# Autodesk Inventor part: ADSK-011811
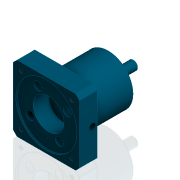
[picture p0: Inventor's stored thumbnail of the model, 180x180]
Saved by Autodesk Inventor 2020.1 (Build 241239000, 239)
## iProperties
Created: 1999-12
Part Number: ADSK-011811
Material: Acier doux
Description: REDUCER,PLANETARY,10/1
Document SubType Name: Modeling
Designer: sspink
Density: 7.86 g/cm^3
Appearance: Bearing Blue
Mass: 6821.52 g
Surface Area: 841.64 cm^2
Volume: 867.878 cm^3
Control State: 0
Checked Out: False
Master: False
Shininess: 0.0
Length Units: 11269
Angle Units: 11279
Time Units: 11290
Mass Units: 11283
Length Display Precision: 3
Angle Display Precision: 2
Compacted: True
Dimensions: 120x120x158 mm
Mass: 6,822 kg
Density: 0.0
Volumn: 0.0
Area: 0.0
PropertySet Name: Model Information
Title: A105198
Author: sspink
Revision Number: -
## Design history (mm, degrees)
node "Solide1"
  node "Extrusion1" dims "d1" = 80, "d2" = 0
  node "Extrusion2" dims "d7" = 32, "d8" = 0
  node "Extrusion3" dims "d12" = 5, "d13" = 0
  node "Extrusion4" dims "d15" = 5, "d16" = 0
  node "Extrusion5" dims "d18" = 36, "d19" = 0
  node "Hole1" dims "d21" = 4.917, "d22" = 4, "d23" = 2, "d24" = 60 deg, "d25" = 16, "d26" = 118 deg, "d65" = 12
  node "Extrusion6" dims "d36" = 32, "d37" = 0
  node "Hole2" dims "d38" = 6.917, "d39" = 9.525, "d40" = 6.35, "d41" = 60 deg, "d42" = 24, "d43" = 118 deg, "d66" = 20
  node "Hole3" dims "d44" = 6, "d45" = 15, "d46" = 23, "d47" = 60 deg, "d48" = 32, "d49" = 118 deg
  node "Extrusion7" dims "d52" = 32, "d53" = 0
  node "Extrusion8" dims "d54" = 4, "d55" = 0
  node "Hole4" dims "d57" = 12, "d58" = 15, "d59" = 23, "d60" = 60 deg, "d61" = 60, "d62" = 118 deg
  node "Chamfer2" dims "d27" = 1, "d28" = 1, "d63" = 45 deg
  node "Chamfer3" dims "d29" = 1, "d30" = 1, "d64" = 45 deg
sketch "Sketch5"
  geometry: C1 r 20 at (0, 0) reference; C2 r 8.25 at (0, 0)
  constraints: 1 centre point, 1 coincident
  dimensions: "d17" = 16.5 diameter of C2
sketch "Sketch6"
  geometry: L1 (0, 0)-(40, 0); L2 (0, 0)-(0, 40); L3 (0, 0)-(-40, 0); L4 (0, 0)-(0, -40); C1 r 45 at (0, 0) reference; A1 r 40 centre (0, 0) between (40, 0) and (0, 40); 4 further points
  constraints: 8 end point, 5 coincident, 4 point on circle, 3 perpendicular, 1 centre point, 1 horizontal
  dimensions: "d20" = 80 diameter of A1
workaxis "Work Axis1"
sketch "Sketch7"
  geometry: L1 (-60, 60)-(60, 60) reference; L2 (-60, -60)-(-60, 60) reference; L3 (60, -60)-(-60, -60) reference; L4 (60, 60)-(60, -60) reference; L5 (-60, 60)-(60, -60); L6 (60, 60)-(-60, -60); L7 (-34.641, 60)-(34.641, -60); L8 (60, 34.641)-(-60, -34.641); A1 r 65 centre (0, 0) between (-45.962, 45.962) and (-45.962, -45.962); A2 r 39 centre (0, 0) between (33.775, 19.5) and (19.5, -33.775); A3 r 80 centre (0, 0) between (-52.915, 60) and (-60, 52.915); A4 r 80 centre (0, 0) between (60, 52.915) and (52.915, 60); A5 r 80 centre (0, 0) between (-60, -52.915) and (-52.915, -60); A6 r 80 centre (0, 0) between (52.915, -60) and (60, -52.915); 5 further points
  constraints: 20 point on line, 16 point on circle, 8 end point, 6 centre point, 3 coincident, 3 concentric, 2 midpoint, 2 perpendicular
  dimensions: "d32" = 80 radius of A3; "d33" = 15 deg angle of L5 L7; "d34" = 130 diameter of A1; "d35" = 78 diameter of A2
node "Corps solides"
node "Corps surfaciques"
sketch "Sketch8"
  geometry: C1 r 28 at (0, 0); C2 r 55.5 at (0, 0); A1 r 80 centre (0, 0) between (-60, -52.915) and (-52.915, -60) reference
  constraints: 2 centre point, 2 coincident
  dimensions: "d50" = 56 diameter of C1; "d51" = 111 diameter of C2
sketch "Sketch1"
  geometry: C1 r 45 at (0, 0)
  constraints: 1 centre point, 1 other
  dimensions: "d0" = 90 diameter of C1
sketch "Sketch2"
  geometry: L1 (0, 0)-(0, 60) reference; L2 (0, 0)-(60, 0) reference; L3 (0, 60)-(60, 60); L4 (60, 60)-(60, 0); L5 (0, 60)-(-60, 60); L6 (-60, 60)-(-60, -60); L7 (-60, -60)-(60, -60); L8 (60, -60)-(60, 0)
  constraints: 16 end point, 4 perpendicular, 3 parallel, 2 vertical, 1 horizontal
  dimensions: "d3" = 60 distance of L1.start L2.end (= 0.5 x d5); "d4" = 60 distance of L1.start L1.end (= 0.5 x d6); "d5" = 120 distance between parallel lines of L4 L6; "d6" = 120 distance between parallel lines of L7 L5
sketch "Sketch3"
  geometry: C1 r 45 at (0, 0) reference; C2 r 34 at (0, 0)
  constraints: 1 centre point, 1 coincident
  dimensions: "d11" = 68 diameter of C2
sketch "Sketch4"
  geometry: C1 r 34 at (0, 0) reference; C2 r 20 at (0, 0)
  constraints: 1 centre point, 1 coincident
  dimensions: "d14" = 40 diameter of C2
sketch "Sketch9"
  geometry: L1 (0, 0)-(0, 105.83) reference; L2 (-32, 105.83)-(-32, 0) reference; L3 (-32, 52.915)-(0, 52.915); 1 further point
  constraints: 2 end point, 2 midpoint, 1 point on line
  dimensions: "d56" = 8.5 distance from line of point (-8.5, 52.915) L1
